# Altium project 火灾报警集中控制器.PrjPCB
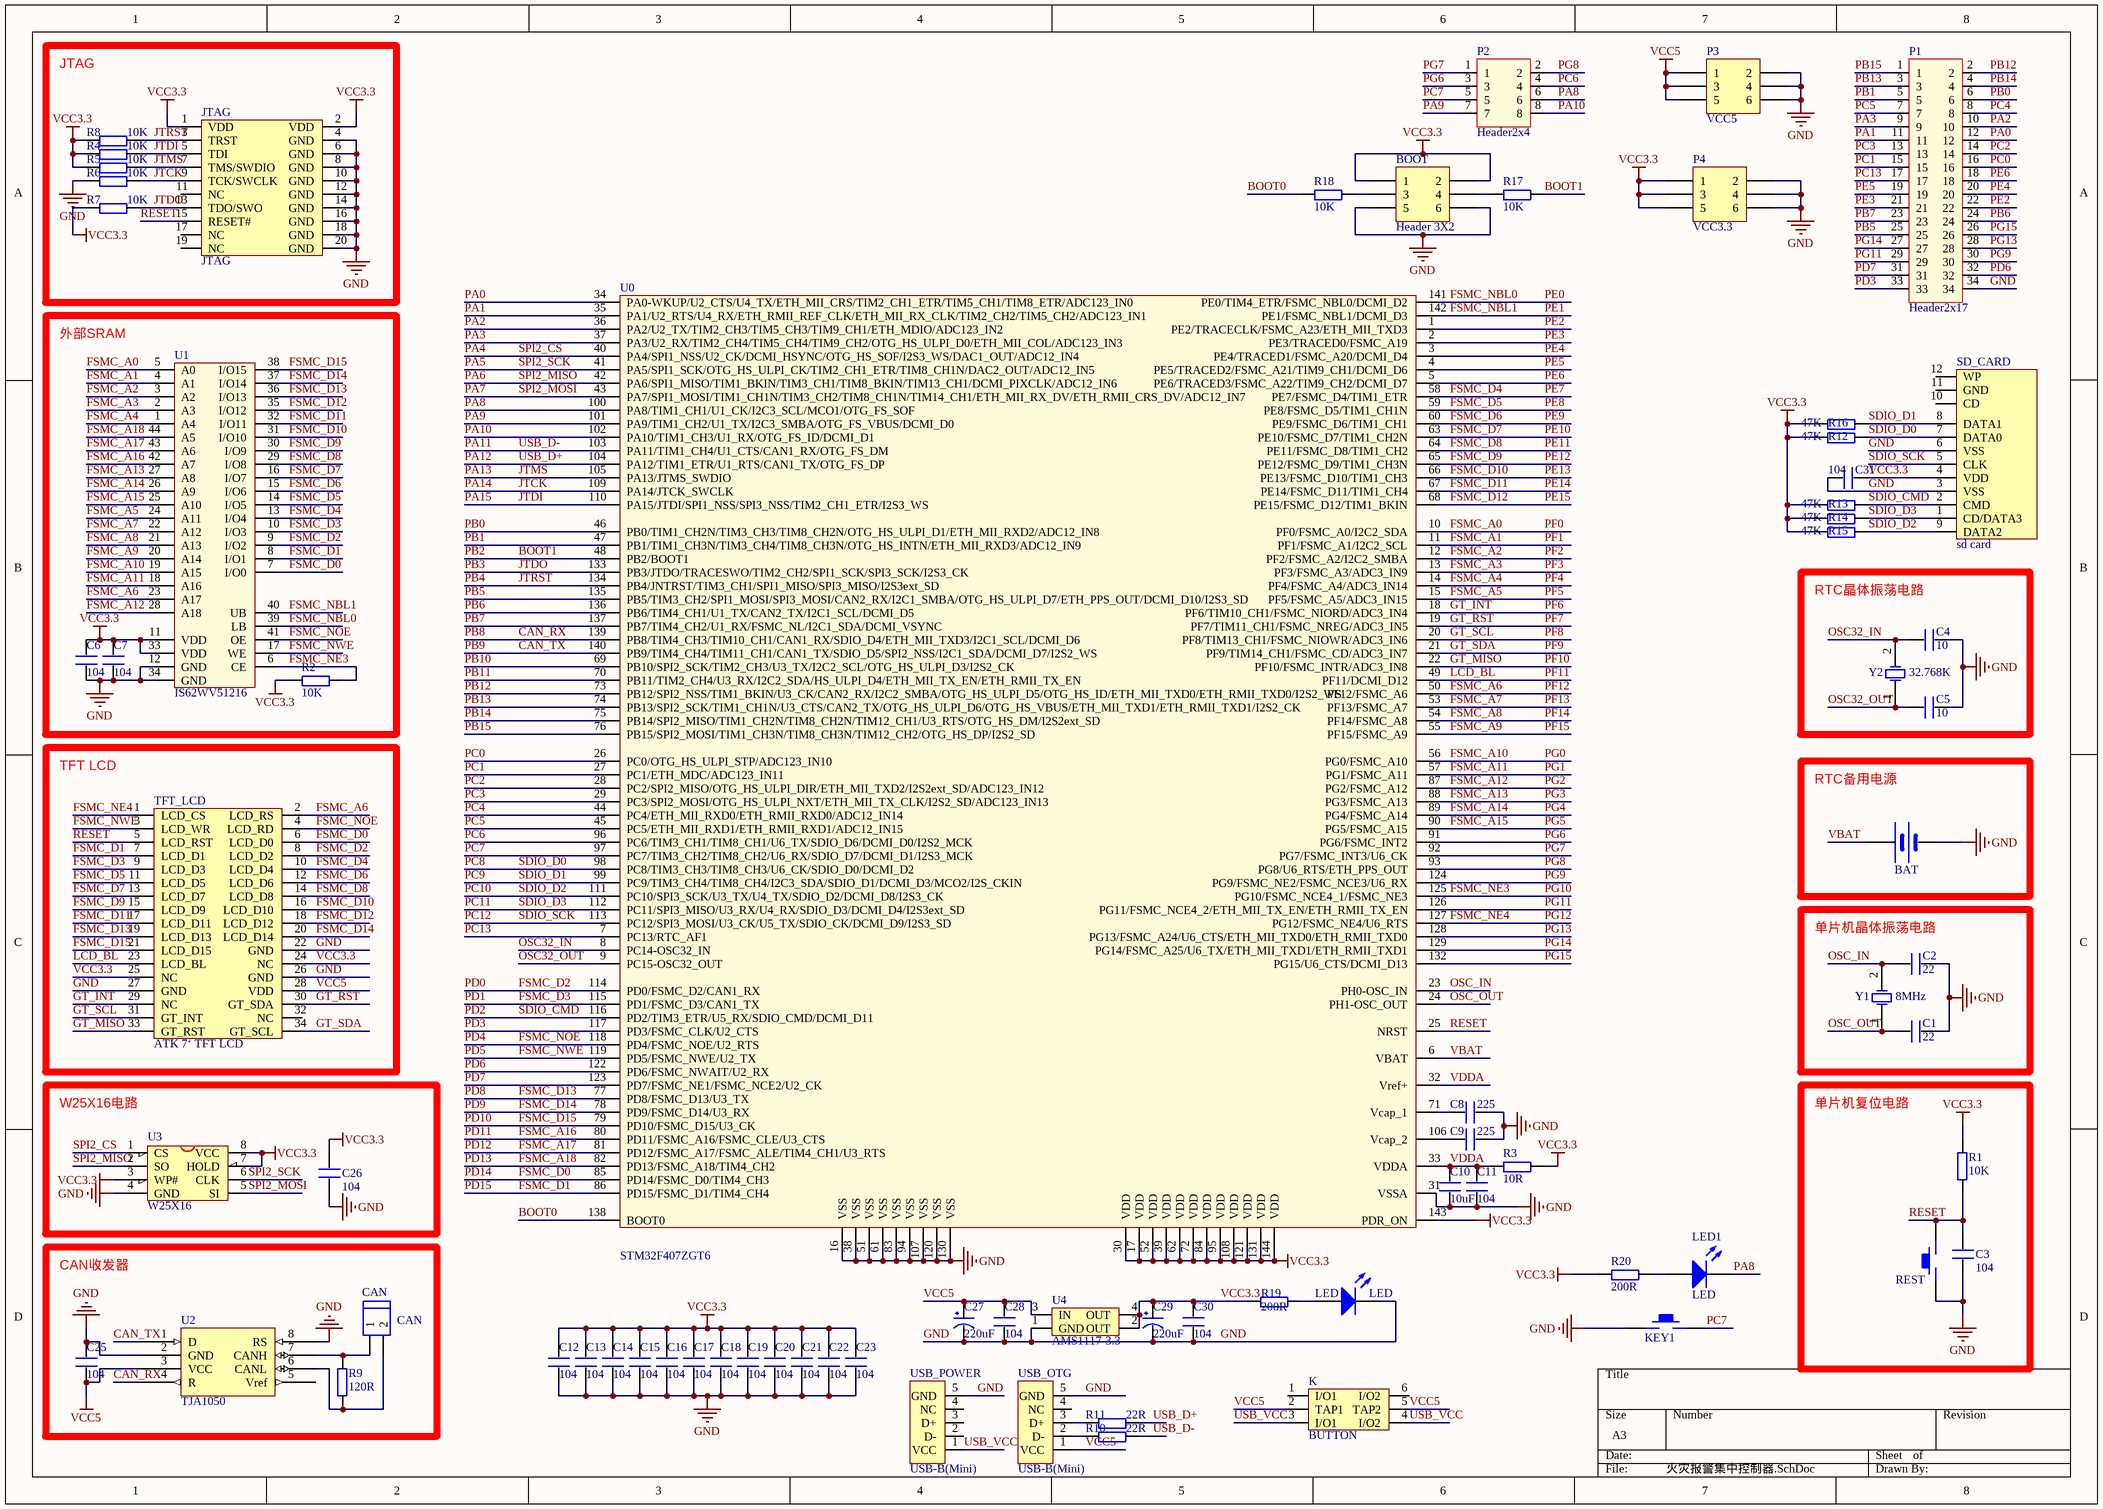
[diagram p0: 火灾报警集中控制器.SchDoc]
1 sheet, 74 parts. Net scope: global (net labels, ports and power ports of the same name join across sheets).
Board file: 火灾报警集中控制器.PcbDoc

## Sheet 火灾报警集中控制器.SchDoc
size A3

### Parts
BAT  BATT  [BATM]  (value not drawn)
BOOT  Header 3X2  [HDR2X3]
C1  22  [0603P]
C2  22  [0603P]
C3  104  [0603P]
C4  10  [0603P]
C5  10  [0603P]
C6  104  [0603P]
C7  104  [0603P]
C8  225  [0603P]
C9  225  [0603P]
C10  10uF  [0603P]
C11  104  [0603P]
C12  104  [0603P]
C13  104  [0603P]
C14  104  [0603P]
C15  104  [0603P]
C16  104  [0603P]
C17  104  [0603P]
C18  104  [0603P]
C19  104  [0603P]
C20  104  [0603P]
C21  104  [0603P]
C22  104  [0603P]
C23  104  [0603P]
C25  104  [0603P]
C26  104  [0603P]
C27  220uF  [CC6.56.5]
C28  104  [0603P]
C29  220uF  [CC6.56.5]
C30  104  [0603P]
C31  104  [0603P]
CAN  CAN  [HEAD2L-0.8]
JTAG  JTAG  [JTAG_20]
K  BUTTON  [BTN8.5*8.5]
KEY1  KEY_M  [KEY_M]  (value not drawn)
LED  LED  [SMDLED]
LED1  LED  [SMDLED]
P1  Header2x17  [Header2x17]
P2  Header2x4  [Header2x4]
P3  VCC5  [HDR2X3]
P4  VCC3.3  [HDR2X3]
R1  10K  [0603P]
R2  10K  [0603P]
R3  10R  [0603P]
R4  10K  [0603P]
R5  10K  [0603P]
R6  10K  [0603P]
R7  10K  [0603P]
R8  10K  [0603P]
R9  120R  [0603P]
R10  22R  [0603P]
R11  22R  [0603P]
R12  47K  [0603P]
R13  47K  [0603P]
R14  47K  [0603P]
R15  47K  [0603P]
R16  47K  [0603P]
R17  10K  [0603P]
R18  10K  [0603P]
R19  200R  [0603P]
R20  200R  [0603P]
REST  KEY_M  [KEY_M]  (value not drawn)
SD_CARD  sd card  [SDCARD_L]
TFT_LCD  ATK 7‘ TFT LCD  [7’ TFT LCD]
U0  STM32F407ZGT6  [LQFP144]
U1  IS62WV51216  [TSOP44]
U2  TJA1050  [SOP-8]
U3  W25X16  [SOIC-8]
U4  AMS1117-3.3  [AMS1117]
USB_OTG  USB-B(Mini)  [USB/SM0.8-6H5]
USB_POWER  USB-B(Mini)  [USB/SM0.8-6H5]
Y1  8MHz  [XTAL_US]
Y2  32.768K  [XTAL32]

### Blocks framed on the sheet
JTAG: JTAG R4-R8
外部SRAM: C6 C7 R2 U1
RTC晶体振荡电路: C4 C5 Y2
TFT LCD: TFT_LCD
RTC备用电源: BAT
单片机晶体振荡电路: C1 C2 Y1
W25X16电路: C26 U3
单片机复位电路: C3 R1 REST
CAN收发器: C25 CAN R9 U2

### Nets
GND: BAT.2(GND) BOOT.5 BOOT.6 C1.1 C2.1 C3.1 C4.2 C5.2 C6.1 C7.1 C8.2 C9.2 C10.1 C11.1 C12.1 C13.1 C14.1 C15.1 C16.1 C17.1 C18.1 C19.1 C20.1 C21.1 C22.1 C23.1 C25.2 C26.1 C27.2(GND) C28.1 C29.2(GND) C30.1 C31.1 JTAG.4(GND) JTAG.6(GND) JTAG.8(GND) JTAG.10(GND) JTAG.12(GND) JTAG.14(GND) JTAG.16(GND) JTAG.18(GND) JTAG.20(GND) KEY1.1 LED.2(K) P1.34 P3.2 P3.4 P3.6 P4.2 P4.4 P4.6 R6.1 REST.1 SD_CARD.3(VSS) SD_CARD.6(VSS) TFT_LCD.22(GND) TFT_LCD.26(GND) TFT_LCD.27(GND) U0.16(VSS) U0.31(VSSA) U0.38(VSS) U0.51(VSS) U0.61(VSS) U0.83(VSS) U0.94(VSS) U0.107(VSS) U0.120(VSS) U0.130(VSS) U1.12(GND) U1.34(GND) U2.2(GND) U2.8(RS) U3.4(GND) U4.1(GND) USB_OTG.5(GND) USB_POWER.5(GND)
VCC3.3: BOOT.1 BOOT.2 C6.2 C7.2 C12.2 C13.2 C14.2 C15.2 C16.2 C17.2 C18.2 C19.2 C20.2 C21.2 C22.2 C23.2 C26.2 C29.1(VCC) C30.2 C31.2 JTAG.1(VDD) JTAG.2(VDD) P4.1 P4.3 P4.5 R1.1 R2.1 R3.2 R4.1 R5.1 R7.1 R8.1 R12.1 R13.1 R14.1 R15.1 R16.1 R19.1 R20.1 SD_CARD.4(VDD) TFT_LCD.24(NC) TFT_LCD.25(NC) U0.17(VDD) U0.30(VDD) U0.39(VDD) U0.52(VDD) U0.62(VDD) U0.72(VDD) U0.84(VDD) U0.95(VDD) U0.108(VDD) U0.121(VDD) U0.131(VDD) U0.143(PDR_ON) U0.144(VDD) U1.11(VDD) U1.33(VDD) U3.3(WP#) U3.7(HOLD) U3.8(VCC) U4.2(OUT) U4.4(OUT)
VCC5: C25.1 C27.1(VCC) C28.2 K.2(TAP1) K.5(TAP2) P3.1 P3.3 P3.5 TFT_LCD.28(VDD) U2.3(VCC) U4.3(IN) USB_OTG.1(VCC)
BOOT0: R18.1 U0.138(BOOT0)
BOOT1: R17.2 U0.48(PB2/BOOT1)  [also labelled PB2]
CAN_RX: U0.139(PB8/TIM4_CH3/TIM10_CH1/CAN1_RX/SDIO_D4/ETH_MII_TXD3/I2C1_SCL/DCMI_D6) U2.4(R)  [also labelled PB8]
CAN_TX: U0.140(PB9/TIM4_CH4/TIM11_CH1/CAN1_TX/SDIO_D5/SPI2_NSS/I2C1_SDA/DCMI_D7/I2S2_WS) U2.1(D)  [also labelled PB9]
FSMC_A0: U0.10(PF0/FSMC_A0/I2C2_SDA) U1.5(A0)  [also labelled PF0]
FSMC_A1: U0.11(PF1/FSMC_A1/I2C2_SCL) U1.4(A1)  [also labelled PF1]
FSMC_A2: U0.12(PF2/FSMC_A2/I2C2_SMBA) U1.3(A2)  [also labelled PF2]
FSMC_A3: U0.13(PF3/FSMC_A3/ADC3_IN9) U1.2(A3)  [also labelled PF3]
FSMC_A4: U0.14(PF4/FSMC_A4/ADC3_IN14) U1.1(A4)  [also labelled PF4]
FSMC_A5: U0.15(PF5/FSMC_A5/ADC3_IN15) U1.24(A11)  [also labelled PF5]
FSMC_A6: TFT_LCD.2(LCD_RS) U0.50(PF12/FSMC_A6) U1.23(A17)  [also labelled PF12]
FSMC_A7: U0.53(PF13/FSMC_A7) U1.22(A12)  [also labelled PF13]
FSMC_A8: U0.54(PF14/FSMC_A8) U1.21(A13)  [also labelled PF14]
FSMC_A9: U0.55(PF15/FSMC_A9) U1.20(A14)  [also labelled PF15]
FSMC_A10: U0.56(PG0/FSMC_A10) U1.19(A15)  [also labelled PG0]
FSMC_A11: U0.57(PG1/FSMC_A11) U1.18(A16)  [also labelled PG1]
FSMC_A12: U0.87(PG2/FSMC_A12) U1.28(A18)  [also labelled PG2]
FSMC_A13: U0.88(PG3/FSMC_A13) U1.27(A8)  [also labelled PG3]
FSMC_A14: U0.89(PG4/FSMC_A14) U1.26(A9)  [also labelled PG4]
FSMC_A15: U0.90(PG5/FSMC_A15) U1.25(A10)  [also labelled PG5]
FSMC_A16: U0.80(PD11/FSMC_A16/FSMC_CLE/U3_CTS) U1.42(A7)  [also labelled PD11]
FSMC_A17: U0.81(PD12/FSMC_A17/FSMC_ALE/TIM4_CH1/U3_RTS) U1.43(A6)  [also labelled PD12]
FSMC_A18: U0.82(PD13/FSMC_A18/TIM4_CH2) U1.44(A5)  [also labelled PD13]
FSMC_D0: TFT_LCD.6(LCD_D0) U0.85(PD14/FSMC_D0/TIM4_CH3) U1.7(I/O0)  [also labelled PD14]
FSMC_D1: TFT_LCD.7(LCD_D1) U0.86(PD15/FSMC_D1/TIM4_CH4) U1.8(I/O1)  [also labelled PD15]
FSMC_D2: TFT_LCD.8(LCD_D2) U0.114(PD0/FSMC_D2/CAN1_RX) U1.9(I/O2)  [also labelled PD0]
FSMC_D3: TFT_LCD.9(LCD_D3) U0.115(PD1/FSMC_D3/CAN1_TX) U1.10(I/O3)  [also labelled PD1]
FSMC_D4: TFT_LCD.10(LCD_D4) U0.58(PE7/FSMC_D4/TIM1_ETR) U1.13(I/O4)  [also labelled PE7]
FSMC_D5: TFT_LCD.11(LCD_D5) U0.59(PE8/FSMC_D5/TIM1_CH1N) U1.14(I/O5)  [also labelled PE8]
FSMC_D6: TFT_LCD.12(LCD_D6) U0.60(PE9/FSMC_D6/TIM1_CH1) U1.15(I/O6)  [also labelled PE9]
FSMC_D7: TFT_LCD.13(LCD_D7) U0.63(PE10/FSMC_D7/TIM1_CH2N) U1.16(I/O7)  [also labelled PE10]
FSMC_D8: TFT_LCD.14(LCD_D8) U0.64(PE11/FSMC_D8/TIM1_CH2) U1.29(I/O8)  [also labelled PE11]
FSMC_D9: TFT_LCD.15(LCD_D9) U0.65(PE12/FSMC_D9/TIM1_CH3N) U1.30(I/O9)  [also labelled PE12]
FSMC_D10: TFT_LCD.16(LCD_D10) U0.66(PE13/FSMC_D10/TIM1_CH3) U1.31(I/O10)  [also labelled PE13]
FSMC_D11: TFT_LCD.17(LCD_D11) U0.67(PE14/FSMC_D11/TIM1_CH4) U1.32(I/O11)  [also labelled PE14]
FSMC_D12: TFT_LCD.18(LCD_D12) U0.68(PE15/FSMC_D12/TIM1_BKIN) U1.35(I/O12)  [also labelled PE15]
FSMC_D13: TFT_LCD.19(LCD_D13) U0.77(PD8/FSMC_D13/U3_TX) U1.36(I/O13)  [also labelled PD8]
FSMC_D14: TFT_LCD.20(LCD_D14) U0.78(PD9/FSMC_D14/U3_RX) U1.37(I/O14)  [also labelled PD9]
FSMC_D15: TFT_LCD.21(LCD_D15) U0.79(PD10/FSMC_D15/U3_CK) U1.38(I/O15)  [also labelled PD10]
FSMC_NBL0: U0.141(PE0/TIM4_ETR/FSMC_NBL0/DCMI_D2) U1.39(LB)  [also labelled PE0]
FSMC_NBL1: U0.142(PE1/FSMC_NBL1/DCMI_D3) U1.40(UB)  [also labelled PE1]
FSMC_NE3: R2.2 U0.125(PG10/FSMC_NCE4_1/FSMC_NE3) U1.6(CE)  [also labelled PG10]
FSMC_NE4: TFT_LCD.1(LCD_CS) U0.127(PG12/FSMC_NE4/U6_RTS)  [also labelled PG12]
FSMC_NOE: TFT_LCD.4(LCD_RD) U0.118(PD4/FSMC_NOE/U2_RTS) U1.41(OE)  [also labelled PD4]
FSMC_NWE: TFT_LCD.3(LCD_WR) U0.119(PD5/FSMC_NWE/U2_TX) U1.17(WE)  [also labelled PD5]
GT_INT: TFT_LCD.29(NC) U0.18(PF6/TIM10_CH1/FSMC_NIORD/ADC3_IN4)  [also labelled PF6]
GT_MISO: TFT_LCD.33(GT_RST) U0.22(PF10/FSMC_INTR/ADC3_IN8)  [also labelled PF10]
GT_RST: TFT_LCD.30(GT_SDA) U0.19(PF7/TIM11_CH1/FSMC_NREG/ADC3_IN5)  [also labelled PF7]
GT_SCL: TFT_LCD.31(GT_INT) U0.20(PF8/TIM13_CH1/FSMC_NIOWR/ADC3_IN6)  [also labelled PF8]
GT_SDA: TFT_LCD.34(GT_SCL) U0.21(PF9/TIM14_CH1/FSMC_CD/ADC3_IN7)  [also labelled PF9]
JTCK: JTAG.9(TCK/SWCLK) R6.2 U0.109(PA14/JTCK_SWCLK)  [also labelled PA14]
JTDI: JTAG.5(TDI) R4.2 U0.110(PA15/JTDI/SPI1_NSS/SPI3_NSS/TIM2_CH1_ETR/I2S3_WS)  [also labelled PA15]
JTDO: JTAG.13(TDO/SWO) R7.2 U0.133(PB3/JTDO/TRACESWO/TIM2_CH2/SPI1_SCK/SPI3_SCK/I2S3_CK)  [also labelled PB3]
JTMS: JTAG.7(TMS/SWDIO) R5.2 U0.105(PA13/JTMS_SWDIO)  [also labelled PA13]
JTRST: JTAG.3(TRST) R8.2 U0.134(PB4/JNTRST/TIM3_CH1/SPI1_MISO/SPI3_MISO/I2S3ext_SD)  [also labelled PB4]
LCD_BL: TFT_LCD.23(LCD_BL) U0.49(PF11/DCMI_D12)  [also labelled PF11]
OSC32_IN: C4.1 U0.8(PC14-OSC32_IN) Y2.2(OSC2)
OSC32_OUT: C5.1 U0.9(PC15-OSC32_OUT) Y2.1(OSC1)
OSC_IN: C2.2 U0.23(PH0-OSC_IN) Y1.2(OSC2)
OSC_OUT: C1.2 U0.24(PH1-OSC_OUT) Y1.1(OSC1)
PA0: P1.12 U0.34(PA0-WKUP/U2_CTS/U4_TX/ETH_MII_CRS/TIM2_CH1_ETR/TIM5_CH1/TIM8_ETR/ADC123_IN0)
PA1: P1.11 U0.35(PA1/U2_RTS/U4_RX/ETH_RMII_REF_CLK/ETH_MII_RX_CLK/TIM2_CH2/TIM5_CH2/ADC123_IN1)
PA2: P1.10 U0.36(PA2/U2_TX/TIM2_CH3/TIM5_CH3/TIM9_CH1/ETH_MDIO/ADC123_IN2)
PA3: P1.9 U0.37(PA3/U2_RX/TIM2_CH4/TIM5_CH4/TIM9_CH2/OTG_HS_ULPI_D0/ETH_MII_COL/ADC123_IN3)
PA4: U0.40(PA4/SPI1_NSS/U2_CK/DCMI_HSYNC/OTG_HS_SOF/I2S3_WS/DAC1_OUT/ADC12_IN4) U3.1(CS)  [also labelled SPI2_CS]
PA5: U0.41(PA5/SPI1_SCK/OTG_HS_ULPI_CK/TIM2_CH1_ETR/TIM8_CH1N/DAC2_OUT/ADC12_IN5) U3.6(CLK)  [also labelled SPI2_SCK]
PA6: U0.42(PA6/SPI1_MISO/TIM1_BKIN/TIM3_CH1/TIM8_BKIN/TIM13_CH1/DCMI_PIXCLK/ADC12_IN6) U3.2(SO)  [also labelled SPI2_MISO]
PA7: U0.43(PA7/SPI1_MOSI/TIM1_CH1N/TIM3_CH2/TIM8_CH1N/TIM14_CH1/ETH_MII_RX_DV/ETH_RMII_CRS_DV/ADC12_IN7) U3.5(SI)  [also labelled SPI2_MOSI]
PA8: LED1.2(K) P2.6 U0.100(PA8/TIM1_CH1/U1_CK/I2C3_SCL/MCO1/OTG_FS_SOF)
PA9: P2.7 U0.101(PA9/TIM1_CH2/U1_TX/I2C3_SMBA/OTG_FS_VBUS/DCMI_D0)
PA10: P2.8 U0.102(PA10/TIM1_CH3/U1_RX/OTG_FS_ID/DCMI_D1)
PA11: R10.2 U0.103(PA11/TIM1_CH4/U1_CTS/CAN1_RX/OTG_FS_DM)  [also labelled USB_D-]
PA12: R11.2 U0.104(PA12/TIM1_ETR/U1_RTS/CAN1_TX/OTG_FS_DP)  [also labelled USB_D+]
PB0: P1.6 U0.46(PB0/TIM1_CH2N/TIM3_CH3/TIM8_CH2N/OTG_HS_ULPI_D1/ETH_MII_RXD2/ADC12_IN8)
PB1: P1.5 U0.47(PB1/TIM1_CH3N/TIM3_CH4/TIM8_CH3N/OTG_HS_INTN/ETH_MII_RXD3/ADC12_IN9)
PB5: P1.25 U0.135(PB5/TIM3_CH2/SPI1_MOSI/SPI3_MOSI/CAN2_RX/I2C1_SMBA/OTG_HS_ULPI_D7/ETH_PPS_OUT/DCMI_D10/I2S3_SD)
PB6: P1.24 U0.136(PB6/TIM4_CH1/U1_TX/CAN2_TX/I2C1_SCL/DCMI_D5)
PB7: P1.23 U0.137(PB7/TIM4_CH2/U1_RX/FSMC_NL/I2C1_SDA/DCMI_VSYNC)
PB10: U0.69(PB10/SPI2_SCK/TIM2_CH3/U3_TX/I2C2_SCL/OTG_HS_ULPI_D3/I2S2_CK)
PB11: U0.70(PB11/TIM2_CH4/U3_RX/I2C2_SDA/HS_ULPI_D4/ETH_MII_TX_EN/ETH_RMII_TX_EN)
PB12: P1.2 U0.73(PB12/SPI2_NSS/TIM1_BKIN/U3_CK/CAN2_RX/I2C2_SMBA/OTG_HS_ULPI_D5/OTG_HS_ID/ETH_MII_TXD0/ETH_RMII_TXD0/I2S2_WS)
PB13: P1.3 U0.74(PB13/SPI2_SCK/TIM1_CH1N/U3_CTS/CAN2_TX/OTG_HS_ULPI_D6/OTG_HS_VBUS/ETH_MII_TXD1/ETH_RMII_TXD1/I2S2_CK)
PB14: P1.4 U0.75(PB14/SPI2_MISO/TIM1_CH2N/TIM8_CH2N/TIM12_CH1/U3_RTS/OTG_HS_DM/I2S2ext_SD)
PB15: P1.1 U0.76(PB15/SPI2_MOSI/TIM1_CH3N/TIM8_CH3N/TIM12_CH2/OTG_HS_DP/I2S2_SD)
PC0: P1.16 U0.26(PC0/OTG_HS_ULPI_STP/ADC123_IN10)
PC1: P1.15 U0.27(PC1/ETH_MDC/ADC123_IN11)
PC2: P1.14 U0.28(PC2/SPI2_MISO/OTG_HS_ULPI_DIR/ETH_MII_TXD2/I2S2ext_SD/ADC123_IN12)
PC3: P1.13 U0.29(PC3/SPI2_MOSI/OTG_HS_ULPI_NXT/ETH_MII_TX_CLK/I2S2_SD/ADC123_IN13)
PC4: P1.8 U0.44(PC4/ETH_MII_RXD0/ETH_RMII_RXD0/ADC12_IN14)
PC5: P1.7 U0.45(PC5/ETH_MII_RXD1/ETH_RMII_RXD1/ADC12_IN15)
PC6: P2.4 U0.96(PC6/TIM3_CH1/TIM8_CH1/U6_TX/SDIO_D6/DCMI_D0/I2S2_MCK)
PC7: KEY1.2 P2.5 U0.97(PC7/TIM3_CH2/TIM8_CH2/U6_RX/SDIO_D7/DCMI_D1/I2S3_MCK)
PC8: R12.2 SD_CARD.7(DATA0) U0.98(PC8/TIM3_CH3/TIM8_CH3/U6_CK/SDIO_D0/DCMI_D2)  [also labelled SDIO_D0]
PC9: R16.2 SD_CARD.8(DATA1) U0.99(PC9/TIM3_CH4/TIM8_CH4/I2C3_SDA/SDIO_D1/DCMI_D3/MCO2/I2S_CKIN)  [also labelled SDIO_D1]
PC10: R15.2 SD_CARD.9(DATA2) U0.111(PC10/SPI3_SCK/U3_TX/U4_TX/SDIO_D2/DCMI_D8/I2S3_CK)  [also labelled SDIO_D2]
PC11: R14.2 SD_CARD.1(CD/DATA3) U0.112(PC11/SPI3_MISO/U3_RX/U4_RX/SDIO_D3/DCMI_D4/I2S3ext_SD)  [also labelled SDIO_D3]
PC12: SD_CARD.5(CLK) U0.113(PC12/SPI3_MOSI/U3_CK/U5_TX/SDIO_CK/DCMI_D9/I2S3_SD)  [also labelled SDIO_SCK]
PC13: P1.17 U0.7(PC13/RTC_AF1)
PD2: R13.2 SD_CARD.2(CMD) U0.116(PD2/TIM3_ETR/U5_RX/SDIO_CMD/DCMI_D11)  [also labelled SDIO_CMD]
PD3: P1.33 U0.117(PD3/FSMC_CLK/U2_CTS)
PD6: P1.32 U0.122(PD6/FSMC_NWAIT/U2_RX)
PD7: P1.31 U0.123(PD7/FSMC_NE1/FSMC_NCE2/U2_CK)
PE2: P1.22 U0.1(PE2/TRACECLK/FSMC_A23/ETH_MII_TXD3)
PE3: P1.21 U0.2(PE3/TRACED0/FSMC_A19)
PE4: P1.20 U0.3(PE4/TRACED1/FSMC_A20/DCMI_D4)
PE5: P1.19 U0.4(PE5/TRACED2/FSMC_A21/TIM9_CH1/DCMI_D6)
PE6: P1.18 U0.5(PE6/TRACED3/FSMC_A22/TIM9_CH2/DCMI_D7)
PG6: P2.3 U0.91(PG6/FSMC_INT2)
PG7: P2.1 U0.92(PG7/FSMC_INT3/U6_CK)
PG8: P2.2 U0.93(PG8/U6_RTS/ETH_PPS_OUT)
PG9: P1.30 U0.124(PG9/FSMC_NE2/FSMC_NCE3/U6_RX)
PG11: P1.29 U0.126(PG11/FSMC_NCE4_2/ETH_MII_TX_EN/ETH_RMII_TX_EN)
PG13: P1.28 U0.128(PG13/FSMC_A24/U6_CTS/ETH_MII_TXD0/ETH_RMII_TXD0)
PG14: P1.27 U0.129(PG14/FSMC_A25/U6_TX/ETH_MII_TXD1/ETH_RMII_TXD1)
PG15: P1.26 U0.132(PG15/U6_CTS/DCMI_D13)
RESET: C3.2 JTAG.15(RESET#) R1.2 REST.2 TFT_LCD.5(LCD_RST) U0.25(NRST)
USB_VCC: K.3(I/O1) K.4(I/O2) USB_POWER.1(VCC)
VBAT: BAT.1(VCC) U0.6(VBAT)
VDDA: C10.2 C11.2 R3.1 U0.32(Vref+) U0.33(VDDA)
NetBOOT_3: BOOT.3 R18.2
NetBOOT_4: BOOT.4 R17.1
NetC8_1: C8.1 U0.71(Vcap_1)
NetC9_1: C9.1 U0.106(Vcap_2)
NetCAN_1: CAN.1 R9.1 U2.7(CANH)
NetCAN_2: CAN.2 R9.2 U2.6(CANL)
NetLED1_1: LED1.1(A) R20.2
NetLED_1: LED.1(A) R19.2
NetR10_1: R10.1 USB_OTG.2(D-)
NetR11_1: R11.1 USB_OTG.3(D+)

Not connected (* = marked no-connect by the designer): JTAG 11(NC) 17(NC) 19(NC); K 1(I/O1) 6(I/O2); SD_CARD 10(CD) 11(GND) 12(WP); TFT_LCD 32(NC); U2 5(Vref); USB_OTG 4(NC); USB_POWER 2(D-) 3(D+) 4(NC)

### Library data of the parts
BAT = BAT
BOOT P3 P4 = Header 3X2: Header, 3-Pin, Dual row
C1-C23 C25 C26 C28 C30 C31 = C
C27 C29 = CAP
CAN = HEAD2
LED LED1 = LED2: Typical RED, GREEN, YELLOW, AMBER GaAs LED
R1-R20 = R
REST = KEY
U0 = STM32F407ZET6
U2 = SN65HVD230D
U3 = W25X16: W25X16;SST25VF016;MX25L1605
U4 = AMS1117
USB_OTG USB_POWER = USB5
Y1 Y2 = XTAL: Crystal Oscillator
